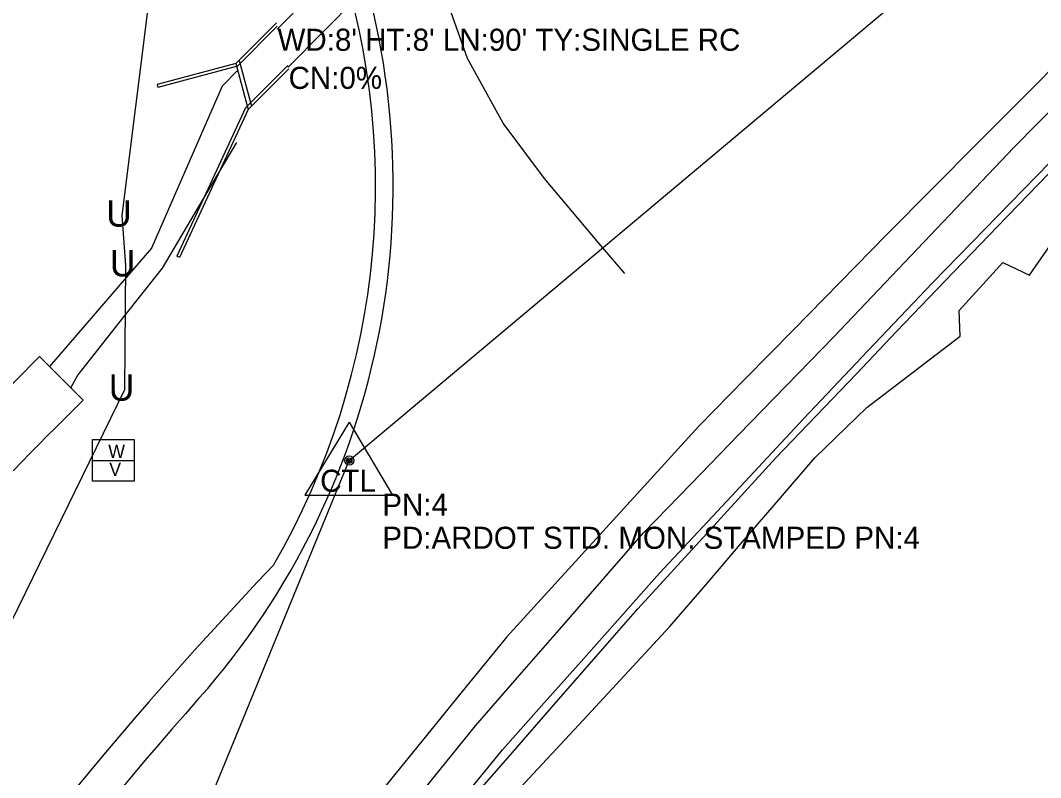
# Model space of a CAD drawing. Extents: x 1282810 to 1284464, y 402460 to 405899.
# Drawn here: x 1283626 to 1283857.3, y 404466.8 to 404638.4 of the extents above; entities that cross this region are included whole.
import ezdxf

# ---------------------------------------------------------------- set-up
doc = ezdxf.new("R2010")
doc.units = 0
for name, color, linetype in [('Default', 7, 'Continuous'), ('MOT_Drainage_Stage 2', 7, 'Continuous'), ('MOT_Proposed Road_Stage 2', 7, 'Continuous'), ('MOT_Shld_Stage 2', 7, 'Continuous'), ('MOT_Stage 1_Conc Ditch Paving', 7, 'Continuous'), ('S_BASELINE', 7, 'Continuous'), ('S_CROSS_DRAIN', 7, 'Continuous'), ('S_CROSS_DRAIN_ANNOT', 7, 'Continuous'), ('S_DITCHLINE', 7, 'Continuous'), ('S_DRG_PT_SYM', 7, 'Continuous'), ('S_EDGE_CONCRETE', 7, 'Continuous'), ('S_EDGE_PAVEMENT', 7, 'Continuous'), ('S_PAVEMENT_CROWN', 7, 'Continuous'), ('S_PRIMARY_CTL', 7, 'Continuous'), ('S_PRIMARY_CTL_ANNOT', 7, 'Continuous'), ('S_SHOULDER', 7, 'Continuous'), ('S_UNDERGROUND_CABLE', 7, 'Continuous'), ('S_WATER_UTILITIES', 7, 'Continuous')]:
    doc.layers.add(name, color=color, linetype=linetype)

msp = doc.modelspace()

# ---------------------------------------------------------------- linework, layer by layer
at = {"layer": 'MOT_Drainage_Stage 2'}
for p, q in [((1283674.89, 404628.64), (1283684.06, 404637.82)), ((1283675.24, 404628.04), (1283684.26, 404637.08)), ((1283675.6, 404629.35), (1283678.4, 404618.94)), ((1283674.89, 404628.64), (1283657.03, 404623.84)), ((1283675.24, 404628.04), (1283657.2, 404623.2)), ((1283674.89, 404628.64), (1283677.69, 404618.23)), ((1283677.09, 404618.58), (1283686.66, 404628.16)), ((1283677.69, 404618.23), (1283686.86, 404627.41)), ((1283657.03, 404623.84), (1283657.2, 404623.2)), ((1283677.09, 404618.58), (1283661.47, 404584.97)), ((1283677.69, 404618.23), (1283662.07, 404584.69)), ((1283662.07, 404584.69), (1283661.47, 404584.97))]:
    msp.add_line(p, q, dxfattribs=at)
at = {"layer": 'MOT_Proposed Road_Stage 2'}
msp.add_lwpolyline([(1283863.48, 404631.16), (1283853.23, 404620.87), (1283842.99, 404610.58), (1283832.75, 404600.29), (1283822.51, 404590), (1283811.84, 404579.12), (1283801.17, 404568.24), (1283790.5, 404557.36), (1283779.83, 404546.48), (1283768.95, 404534.55), (1283758.06, 404522.62), (1283747.17, 404510.69), (1283736.28, 404498.75), (1283727.17, 404487.56), (1283718.07, 404476.36), (1283708.96, 404465.16)], dxfattribs=at)
msp.add_lwpolyline([(1283863.48, 404631.16), (1283853.23, 404620.87), (1283842.99, 404610.58), (1283832.75, 404600.29), (1283822.51, 404590), (1283811.84, 404579.12), (1283801.17, 404568.24), (1283790.5, 404557.36), (1283779.83, 404546.48), (1283768.95, 404534.55), (1283758.06, 404522.62), (1283747.17, 404510.69), (1283736.28, 404498.75), (1283727.17, 404487.56), (1283718.07, 404476.36), (1283708.96, 404465.16)], dxfattribs=at)
for centre, radius, start, end in [((1283535.54, 404600.86), 175, 318.458, 19.8404), ((1284344.24, 403884.33), 905.47, 138.45801, 157.33333)]:
    msp.add_arc(centre, radius, start, end, dxfattribs=at)
at = {"layer": 'MOT_Shld_Stage 2'}
for centre, radius, start, end in [((1283535.54, 404600.86), 171, 329.8592, 19.8404), ((1284344.24, 403884.33), 913.47, 136.3373, 157.33333)]:
    msp.add_arc(centre, radius, start, end, dxfattribs=at)
at = {"layer": 'MOT_Stage 1_Conc Ditch Paving'}
msp.add_line((1283640.27, 404552.35), (1283636.06, 404556.62), dxfattribs=at)
for points in [[(1283636.06, 404556.62), (1283630.35, 404562.28), (1283613.68, 404545.41)], [(1283624.42, 404536.37), (1283626.35, 404538.35), (1283628.27, 404540.32), (1283630.21, 404542.28), (1283632.14, 404544.24), (1283634.09, 404546.2), (1283636.04, 404548.15), (1283637.99, 404550.09), (1283640.27, 404552.35)]]:
    msp.add_lwpolyline(points, dxfattribs=at)
at = {"layer": 'S_BASELINE'}
for p, q in [((1283700.58, 404538.68), (1284334.82, 405070.64)), ((1283396.79, 403800.11), (1283700.58, 404538.68))]:
    msp.add_line(p, q, dxfattribs=at)
at = {"layer": 'S_CROSS_DRAIN'}
for p, q in [((1283684.33, 404636.51), (1283747.67, 404700.67)), ((1283750.34, 404692.1), (1283686.84, 404627.88))]:
    msp.add_line(p, q, dxfattribs=at)
at = {"layer": 'S_DITCHLINE'}
for points in [[(1283728.14, 404461.7), (1283737.59, 404472.54), (1283747.04, 404483.38), (1283756.5, 404494.22), (1283765.95, 404505.06), (1283781.61, 404522.16), (1283797.27, 404539.26), (1283806.4, 404548.8), (1283815.52, 404558.34), (1283824.64, 404567.88), (1283833.76, 404577.42), (1283847.61, 404591.78), (1283861.45, 404606.14), (1283871.22, 404616), (1283880.98, 404625.85), (1283890.75, 404635.71), (1283900.52, 404645.57), (1283918.13, 404663.1), (1283935.73, 404680.62), (1283947.35, 404691.8), (1283958.97, 404702.98)], [(1283675.31, 404627.1), (1283671.74, 404623.47), (1283663.75, 404605.12), (1283655.76, 404586.77), (1283644.88, 404574.15), (1283632.66, 404559.99)], [(1283675, 404610.75), (1283668.27, 404599.38), (1283658.14, 404582.28), (1283648.61, 404570.21), (1283639.09, 404558.13), (1283637.47, 404555.19)], [(1283731.94, 404456.53), (1283742.27, 404467.67), (1283752.6, 404478.8), (1283762.93, 404489.94), (1283773.26, 404501.08), (1283781.46, 404510.63), (1283789.66, 404520.17), (1283797.87, 404529.71), (1283806.07, 404539.26), (1283817.86, 404550.72), (1283828.44, 404558.8), (1283839.03, 404566.88), (1283838.85, 404572.67), (1283848.75, 404583.51), (1283854.79, 404580.67), (1283863.94, 404593.97)]]:
    msp.add_lwpolyline(points, dxfattribs=at)
at = {"layer": 'S_DRG_PT_SYM'}
for points in [[(1283684.33, 404636.51), (1283684.33, 404636.56), (1283684.33, 404636.51), (1283684.28, 404636.51), (1283684.33, 404636.51), (1283684.33, 404636.46), (1283684.33, 404636.51), (1283684.38, 404636.51)], [(1283686.84, 404627.88), (1283686.84, 404627.93), (1283686.84, 404627.88), (1283686.79, 404627.88), (1283686.84, 404627.88), (1283686.84, 404627.83), (1283686.84, 404627.88), (1283686.89, 404627.88)]]:
    msp.add_lwpolyline(points, dxfattribs=at)
at = {"layer": 'S_EDGE_CONCRETE'}
msp.add_lwpolyline([(1283719.6, 404453.87), (1283735.28, 404473.1), (1283744.19, 404483.12), (1283753.11, 404493.13), (1283762.02, 404503.15), (1283770.93, 404513.17), (1283787.22, 404530.64), (1283803.5, 404548.11), (1283818.13, 404563.52), (1283832.76, 404578.93), (1283841.62, 404588), (1283850.47, 404597.08), (1283859.32, 404606.15), (1283868.18, 404615.22), (1283877.88, 404625.06), (1283887.59, 404634.89), (1283897.3, 404644.73), (1283907.01, 404654.57), (1283922.85, 404670.37), (1283938.69, 404686.18), (1283948.28, 404695.36), (1283957.88, 404704.55)], dxfattribs=at)
at = {"layer": 'S_EDGE_PAVEMENT'}
msp.add_lwpolyline([(1283863.48, 404631.16), (1283853.23, 404620.87), (1283842.99, 404610.58), (1283832.75, 404600.29), (1283822.51, 404590), (1283811.84, 404579.12), (1283801.17, 404568.24), (1283790.5, 404557.36), (1283779.83, 404546.48), (1283768.95, 404534.55), (1283758.06, 404522.62), (1283747.17, 404510.69), (1283736.28, 404498.75), (1283727.17, 404487.56), (1283718.07, 404476.36), (1283708.96, 404465.16)], dxfattribs=at)
at = {"layer": 'S_PAVEMENT_CROWN'}
msp.add_lwpolyline([(1283763.06, 404581.02), (1283757.18, 404587.96), (1283744.84, 404602.59), (1283735.46, 404615.11), (1283727.38, 404629.8), (1283720.71, 404648.55), (1283716.16, 404664.6), (1283711.6, 404680.66), (1283706.63, 404699.87), (1283701.66, 404719.08), (1283696.55, 404740.81), (1283691.44, 404762.55), (1283688.17, 404778.09), (1283684.91, 404793.63), (1283681.52, 404817.08), (1283678.14, 404840.54), (1283676.65, 404858.67), (1283675.16, 404876.81), (1283674.46, 404891.63), (1283673.76, 404906.45)], dxfattribs=at)
at = {"layer": 'S_PRIMARY_CTL'}
for p, q in [((1283700.58, 404547.38), (1283690.55, 404530.86)), ((1283700.58, 404547.38), (1283710.41, 404530.86)), ((1283690.55, 404530.86), (1283710.41, 404530.86))]:
    msp.add_line(p, q, dxfattribs=at)
for radius in [1.04, 0.609, 0.344]:
    msp.add_circle((1283700.58, 404538.68), radius, dxfattribs=at)
at = {"layer": 'S_SHOULDER'}
msp.add_lwpolyline([(1283710.69, 404455.61), (1283719.93, 404467.08), (1283729.18, 404478.54), (1283738.71, 404489.49), (1283748.24, 404500.43), (1283757.77, 404511.37), (1283767.29, 404522.31), (1283778.07, 404533.41), (1283788.84, 404544.51), (1283799.61, 404555.62), (1283810.38, 404566.72), (1283820.59, 404577.45), (1283830.8, 404588.17), (1283841.01, 404598.9), (1283851.22, 404609.63), (1283862.18, 404620.7)], dxfattribs=at)
at = {"layer": 'S_UNDERGROUND_CABLE'}
for p, q in [((1283649.11, 404594.2), (1283660.12, 404681.79)), ((1283649.97, 404582.94), (1283649.11, 404594.2)), ((1283649.71, 404554.77), (1283649.97, 404582.94)), ((1283613.96, 404481.66), (1283649.71, 404554.77))]:
    msp.add_line(p, q, dxfattribs=at)
at = {"layer": 'S_WATER_UTILITIES'}
for p, q in [((1283642.41, 404543.41), (1283651.82, 404543.41)), ((1283642.41, 404534), (1283642.41, 404543.41)), ((1283651.82, 404543.41), (1283651.82, 404534)), ((1283642.41, 404538.72), (1283651.82, 404538.72)), ((1283651.82, 404534), (1283642.41, 404534))]:
    msp.add_line(p, q, dxfattribs=at)

# ---------------------------------------------------------------- texts
at = {"layer": 'Default'}
for p in [(1283645.48, 404591.66), (1283646.34, 404580.39), (1283646.08, 404552.22)]:
    msp.add_text('U', height=6, rotation=360, dxfattribs=at).set_placement(p)
at = {"layer": 'S_CROSS_DRAIN_ANNOT'}
for s, p in [("WD:8' HT:8' LN:90' TY:SINGLE RC", (1283684.33, 404631.51)), ('CN:0%', (1283686.84, 404622.88))]:
    msp.add_text(s, height=5, dxfattribs=at).set_placement(p)
at = {"layer": 'S_PRIMARY_CTL'}
msp.add_text('CTL', height=5, rotation=360, dxfattribs=at).set_placement((1283693.99, 404531.6))
at = {"layer": 'S_PRIMARY_CTL_ANNOT'}
for s, p in [('PN:4', (1283708.08, 404526.18)), ('PD:ARDOT STD. MON. STAMPED PN:4', (1283708.08, 404518.68))]:
    msp.add_text(s, height=5, dxfattribs=at).set_placement(p)
at = {"layer": 'S_WATER_UTILITIES'}
for s, p in [('W', (1283645.96, 404539.26)), ('V', (1283646.19, 404535.19))]:
    msp.add_text(s, height=3, rotation=360, dxfattribs=at).set_placement(p)

doc.saveas('drawing.dxf')
